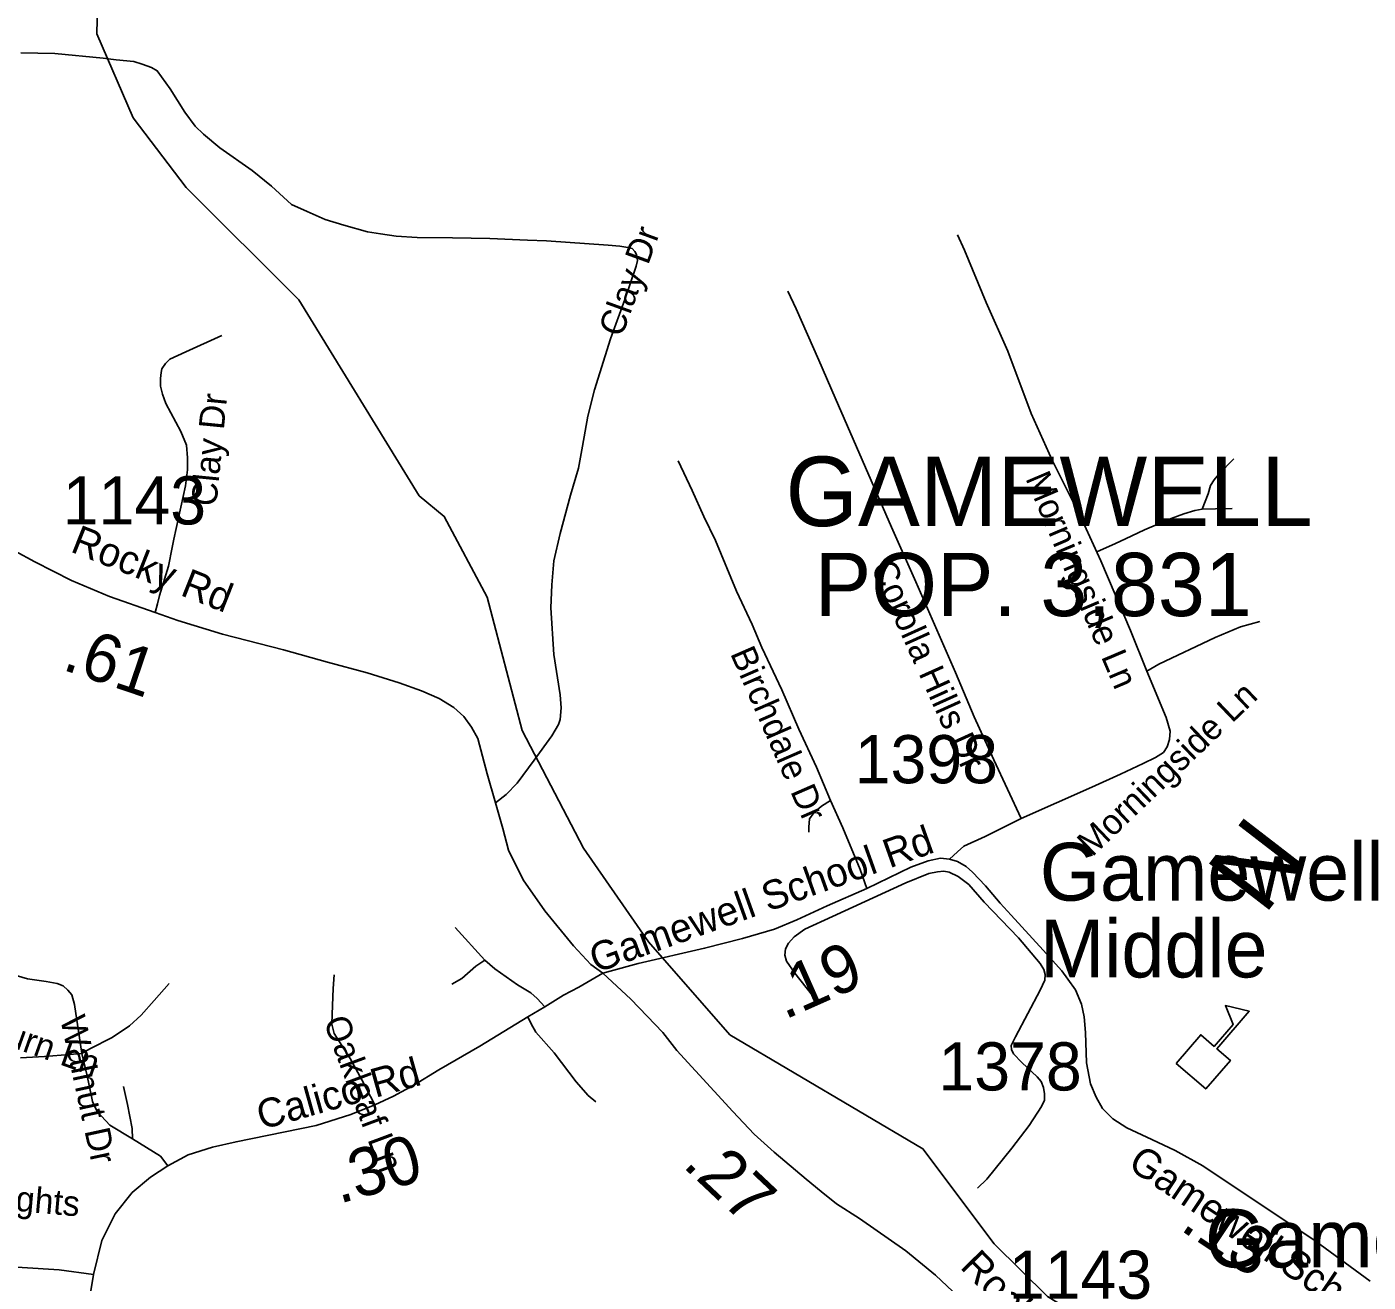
# Model space of a CAD drawing. Extents: x 1159738 to 1321356, y 736314 to 882035.
# Drawn here: x 1227136 to 1230616, y 781529 to 784785 of the extents above; entities that cross this region are included whole.
import ezdxf

# ---------------------------------------------------------------- set-up
doc = ezdxf.new("R2010")
doc.units = 0
for name, color, linetype in [('Exist Boundary Political Fire Districts Label', 7, 'Continuous'), ('Exist Civil Demographics City Label', 7, 'Continuous'), ('Exist Cultural Educational Facility Elementary Label', 7, 'Continuous'), ('Exist Cultural Educational Facility Middle CELL', 7, 'Continuous'), ('Exist Cultural Educational Facility Middle Label', 7, 'Continuous'), ('Exist Hydrographic Creek Single Shore', 7, 'Continuous'), ('Exist Hydrographic Misc Water Feature', 7, 'Continuous'), ('Exist Road Non-System Type 51', 7, 'Continuous'), ('Exist Road Non-System Type 51 Label', 7, 'Continuous'), ('Exist Road Secondary Mileage Hundredths English Label', 7, 'Continuous'), ('Exist Road Secondary Type 51 Attributed', 7, 'Continuous'), ('Exist Road Secondary Type 51 Label', 7, 'Continuous'), ('Exist Road Secondary Type 51 Number Label', 7, 'Continuous')]:
    doc.layers.add(name, color=color, linetype=linetype)

msp = doc.modelspace()

# ---------------------------------------------------------------- linework, layer by layer
at = {"layer": 'Exist Cultural Educational Facility Middle CELL'}
msp.add_lwpolyline([(1230117.6, 782096.4), (1230181.4, 782170.7), (1230216.3, 782140.6), (1230265.3, 782197.6), (1230245.5, 782246.6), (1230307.4, 782231.8), (1230223.6, 782134.4), (1230258.5, 782104.3), (1230194.6, 782030.1)], close=True, dxfattribs=at)
at = {"layer": 'Exist Hydrographic Creek Single Shore'}
msp.add_lwpolyline([(1231130.1, 780564), (1231004, 780616.7), (1230431, 781015.6), (1230170, 781257.2), (1229784, 781491.4), (1229646, 781628.8), (1229460.9, 781875.3), (1228960, 782171), (1228749, 782411.5), (1228579.9, 782654.6), (1228420.9, 782959.7), (1228330, 783306.2), (1228218.9, 783515.3), (1228153.9, 783569.1)], dxfattribs=at)
at = {"layer": 'Exist Hydrographic Misc Water Feature'}
msp.add_lwpolyline([(1228153.9, 783569.1), (1227841.9, 784077.5), (1227548.9, 784369), (1227411.8, 784549), (1227317.9, 784767.5), (1227323.9, 785026.8), (1227422.9, 785290.6), (1227668.9, 785774.9)], dxfattribs=at)
at = {"layer": 'Exist Road Non-System Type 51'}
for points in [[(1228351.5, 782772.3), (1228379.7, 782794.1), (1228407.8, 782823.1), (1228452.2, 782883), (1228498.4, 782946.6), (1228515.7, 782975.6), (1228519.3, 782988.3), (1228522, 783019.2), (1228519.3, 783052.7), (1228503, 783157.1), (1228495.7, 783278), (1228498.4, 783337.9), (1228503, 783400.5), (1228519.3, 783471.3), (1228546.5, 783570.2), (1228567.3, 783640.6), (1228577.3, 783697.7), (1228591.8, 783775.8), (1228609, 783843.8), (1228650.6, 783975.9), (1228687.8, 784078.5), (1228716.7, 784164.9), (1228720.3, 784179.4), (1228717.6, 784194.8), (1228713.1, 784203), (1228706.7, 784210.3), (1228695, 784213), (1228674.1, 784216.6), (1228644.2, 784219.3), (1228484.6, 784230.2), (1228435, 784231.9), (1228337.1, 784236.4), (1228240, 784238.2), (1228148.4, 784239.2), (1228094, 784242.8), (1228053.2, 784248.2), (1228019.7, 784253.7), (1227958, 784270.9), (1227910, 784285.4), (1227862.8, 784306.3), (1227822.4, 784324.4), (1227770.7, 784372.5), (1227720.8, 784412.4), (1227636.5, 784471.4), (1227594.7, 784506.8), (1227573, 784527.7), (1227545.8, 784564), (1227508, 784624.5), (1227474.4, 784671.6), (1227459, 784679.8), (1227435.4, 784688.9), (1227413.7, 784695.2), (1227367.4, 784699.8), (1227333.9, 784704.3), (1227208.2, 784716), (1227120.3, 784717.8)], [(1229550.8, 784246), (1229568.3, 784205.9), (1229624.8, 784070.7), (1229681.3, 783943.7), (1229741.8, 783782.3), (1229796.2, 783661.3), (1229875.1, 783504.3), (1229922.6, 783400.1), (1229999, 783219.6), (1230041.7, 783114)], [(1229110.2, 784099.4), (1229131.9, 784054.1), (1229190.6, 783920.4), (1229233.5, 783823), (1229312, 783642.4), (1229379.6, 783487.8), (1229442.4, 783345.9), (1229545.6, 783110.1), (1229594, 782995.1), (1229644.8, 782884.4), (1229715.4, 782731.7)], [(1227641.5, 783985), (1227548.1, 783942.3), (1227507.3, 783923.3), (1227495.5, 783912.4), (1227486.4, 783897.9), (1227484.6, 783888.8), (1227482.8, 783873.4), (1227482.8, 783853.4), (1227488.2, 783832.5), (1227496.4, 783808), (1227535.4, 783735.4), (1227549.9, 783700), (1227552.6, 783667.4), (1227552.6, 783636.5), (1227547.2, 783594.8), (1227517.3, 783456.3), (1227512.7, 783434.5), (1227503.7, 783386.4), (1227480.1, 783310.6), (1227474.6, 783288.8), (1227469.2, 783266.1)], [(1229095.1, 783065.5), (1229043.2, 783175.3), (1229017.8, 783235.2), (1228976.7, 783321.5), (1228922.4, 783453.2), (1228892.2, 783515.5), (1228862, 783582.9), (1228825.7, 783659.5)], [(1230185.2, 783534.5), (1230200.9, 783574.2), (1230206.9, 783596), (1230216.7, 783610.3), (1230228.7, 783625.4), (1230267.1, 783664.6)], [(1229911.7, 783423.5), (1229960.7, 783445.1), (1229986.4, 783456.9), (1230035.4, 783480.3), (1230104.6, 783509.7), (1230137.7, 783521.7), (1230166.3, 783530.8), (1230185.2, 783534.5), (1230219.8, 783535.3), (1230263.5, 783536.1)], [(1230041.7, 783114), (1230072.9, 783131.8), (1230219.1, 783201.7), (1230284.7, 783228.8), (1230335.3, 783243.2)], [(1229715.4, 782731.7), (1229899.1, 782812.7), (1229973.1, 782846.6), (1230032.1, 782874.3), (1230064.6, 782889.9), (1230085, 782903.2), (1230094.6, 782917.6), (1230100.7, 782936.9), (1230101.9, 782958.6), (1230092.2, 782993.5), (1230041.7, 783114)], [(1229220.8, 782778.4), (1229184.5, 782865), (1229139.2, 782963.9), (1229095.1, 783065.5)], [(1229220.8, 782778.4), (1229197.8, 782763.9), (1229177.9, 782746.4), (1229166.4, 782730.6), (1229164.6, 782708.9), (1229165.2, 782696.2)], [(1229220.8, 782778.4), (1229252.8, 782707.7), (1229297.6, 782599.4), (1229315.1, 782549.8)], [(1229715.4, 782731.7), (1229622.4, 782685.2), (1229567.3, 782660.4), (1229550.4, 782645.3), (1229529.9, 782626.5)], [(1229882.6, 782176.8), (1229879, 782217.4), (1229871.8, 782250), (1229856.7, 782287.5), (1229836.7, 782315.4), (1229821, 782336.5), (1229772.7, 782390.5), (1229689.9, 782481.3), (1229661.4, 782512.1), (1229622.9, 782557.3), (1229589.6, 782592.4), (1229573.3, 782606.9), (1229550.4, 782620.4)], [(1229191.1, 782252.2), (1229128.2, 782330.2), (1229106.5, 782361.7), (1229102.8, 782377.4), (1229104.6, 782393.8), (1229111.9, 782408.3), (1229127, 782424.6), (1229154.8, 782444.6), (1229226.2, 782477.8), (1229416.4, 782565.2), (1229476.3, 782588.8), (1229498.7, 782593.7), (1229515, 782594.9), (1229528.9, 782592.5), (1229552.5, 782581.6), (1229579.7, 782561), (1229619.6, 782515), (1229708.9, 782422.6), (1229765.1, 782356), (1229774.8, 782339.7), (1229777.8, 782327), (1229777.2, 782312.5), (1229765.1, 782286.5), (1229700.9, 782165.1), (1229690, 782142.7), (1229690.6, 782132.5), (1229695.5, 782121.6), (1229717.8, 782098.6), (1229757, 782062), (1229767.3, 782049.3), (1229774, 782034.2), (1229775.8, 782017.8), (1229776.4, 782001.5), (1229768.5, 781984.6), (1229736.5, 781935), (1229691.8, 781876.6), (1229626.5, 781796.1), (1229602.3, 781772.5)], [(1227278.9, 782122.6), (1227259.6, 782249.3), (1227252.4, 782274.1), (1227242.1, 782286.8), (1227230, 782297.7), (1227214.9, 782303.7), (1227186.5, 782308.6), (1227137.5, 782315.8), (1227108.5, 782324.3), (1227042, 782355.8), (1226957.4, 782402.9), (1226955, 782408.9), (1226955.6, 782423.5), (1226966.5, 782443.4), (1226999.7, 782491.6), (1227031.8, 782522.4), (1227068.6, 782549.7), (1227088.5, 782563.3)], [(1228324.5, 782364), (1228247.1, 782448.7)], [(1228238.7, 782301.7), (1228264.7, 782316.8), (1228301, 782348.3), (1228324.5, 782364)], [(1228324.5, 782364), (1228350.5, 782341.6), (1228408.6, 782300.5), (1228443.6, 782279.9), (1228460, 782264.8), (1228479.6, 782243.3)], [(1228038.7, 781989), (1228004.8, 782054.1), (1227974.6, 782109.2), (1227932.9, 782173.9), (1227926.9, 782198.1), (1227928.1, 782224.1), (1227930.5, 782290.9), (1227933, 782325.9)], [(1227504.8, 782303.6), (1227466.1, 782259.4), (1227432.3, 782222), (1227402.1, 782193.6), (1227357.4, 782163.3), (1227299.3, 782134.3), (1227278.9, 782122.6)], [(1228436.1, 782217.3), (1228444, 782198.7), (1228456.7, 782177.5), (1228504.4, 782123.6), (1228561.3, 782048.6), (1228592.7, 782012.9), (1228612.1, 781996.6)], [(1229885.4, 782097.8), (1229882.6, 782176.8)], [(1227278.9, 782122.6), (1227246.8, 782119.4), (1227181.5, 782114), (1227119.8, 782111.2)], [(1227501.9, 781830.7), (1227482.6, 781856.1), (1227410.1, 781900.7), (1227351.4, 781936.2), (1227318.2, 781971.9), (1227306.7, 781997.3), (1227292.2, 782064.5), (1227278.9, 782122.6)], [(1230055, 781898.8), (1229989.7, 781929.7), (1229953.6, 781952.9), (1229926.9, 781979.7), (1229910.6, 782008.8), (1229895.5, 782043.7), (1229885.4, 782097.8)], [(1227410.1, 781900.7), (1227409.5, 781927.9), (1227397.4, 781989.6), (1227386.5, 782036.8)]]:
    msp.add_lwpolyline(points, dxfattribs=at)
at = {"layer": 'Exist Road Secondary Type 51 Attributed'}
for points in [[(1227106, 783425.5), (1227156.3, 783397.3), (1227251.6, 783348.9), (1227350.6, 783307.9), (1227469.2, 783266.1), (1227527.7, 783245.1), (1227643.7, 783210.1), (1227801.5, 783169.1), (1227915.8, 783137.5), (1228018.7, 783109.4), (1228101.5, 783083.8), (1228159.5, 783063.3), (1228205.6, 783042.8), (1228243.6, 783020.1), (1228270, 782996.2), (1228289.6, 782968.9), (1228305.8, 782939), (1228330.6, 782847.6), (1228351.5, 782772.3), (1228370.6, 782705.5), (1228385.9, 782650), (1228423.5, 782572.3), (1228479.6, 782492.4), (1228553.9, 782401.9), (1228598.9, 782352.7), (1228629.9, 782330.3)], [(1228629.9, 782330.3), (1228649.3, 782335.7), (1228721.7, 782355.6), (1228894.4, 782395.4), (1228992.3, 782420.2), (1229075.8, 782445), (1229133.8, 782469.2), (1229212.1, 782505.5), (1229315.1, 782549.8), (1229429.4, 782605.7), (1229474.8, 782622.1), (1229506.8, 782628.7), (1229529.9, 782626.5), (1229550.4, 782620.4)], [(1228629.9, 782330.3), (1228567.7, 782294.6), (1228528.4, 782273.4), (1228479.6, 782243.3), (1228436.1, 782217.3), (1228310.9, 782141.1), (1228205.2, 782080.1), (1228140.1, 782040.3), (1228087.5, 782011.9), (1228038.7, 781989), (1227976.2, 781964), (1227886.3, 781935), (1227678.7, 781893.1), (1227617.2, 781879.6), (1227554.8, 781859.4), (1227501.9, 781830.7), (1227456.8, 781801.8), (1227408.8, 781761.4), (1227364.7, 781706.6), (1227330.1, 781637.4), (1227308.7, 781549)], [(1228629.9, 782330.3), (1228703.2, 782263.2), (1228745.6, 782218.8), (1228785.9, 782176.4), (1228822.2, 782130.1), (1228967.5, 781972), (1229022.9, 781913.1), (1229074.9, 781866.1), (1229157.8, 781796.2), (1229196.6, 781764), (1229236.7, 781732.4), (1229296.4, 781694), (1229416.7, 781610.3), (1229493.2, 781546.8), (1229596.8, 781449.6), (1229714.5, 781332)], [(1230621, 781531.9), (1230478.2, 781636.3), (1230187.4, 781830.7), (1230115.3, 781870.3), (1230055, 781898.8)], [(1227308.7, 781549), (1227219.7, 781561.4), (1227123.6, 781566.8), (1227018.1, 781572.7), (1226869.7, 781577.2), (1226710, 781582.8), (1226530.8, 781590.7), (1226349.5, 781603.1), (1226192, 781618.5), (1226038.8, 781631)], [(1227308.7, 781549), (1227302.3, 781506.2), (1227300.3, 781456.2), (1227303.2, 781336.1), (1227309, 781166.6), (1227311.9, 781044.5), (1227305.9, 780963.8), (1227303.3, 780924.7), (1227287.9, 780809.4), (1227272.6, 780715.6), (1227261.1, 780609.9), (1227251.4, 780496), (1227246.7, 780448.4), (1227235.1, 780411.9)]]:
    msp.add_lwpolyline(points, dxfattribs=at)

# ---------------------------------------------------------------- texts
at = {"layer": 'Exist Boundary Political Fire Districts Label'}
msp.add_text('N', height=196.8, rotation=52.3723, dxfattribs=at).set_placement((1230345.8, 782477.8))
at = {"layer": 'Exist Civil Demographics City Label'}
for s, height, p in [('GAMEWELL', 180.45, (1229104.4, 783490.2)), ('POP. 3,831', 164.04, (1229180.3, 783256.8))]:
    msp.add_text(s, height=height, dxfattribs=at).set_placement(p)
at = {"layer": 'Exist Cultural Educational Facility Elementary Label'}
msp.add_text('Gamewell', height=150, dxfattribs=at).set_placement((1230192.9, 781567.3))
at = {"layer": 'Exist Cultural Educational Facility Middle Label'}
for s, p in [('Gamewell', (1229764.1, 782518.7)), ('Middle', (1229764.1, 782319.5))]:
    msp.add_text(s, height=150, dxfattribs=at).set_placement(p)
at = {"layer": 'Exist Road Non-System Type 51 Label'}
for s, height, rotation, p in [('Clay Dr', 65.62, 69.9979, (1228679.2, 783977.7)), ('Clay Dr', 65.62, 84.4112, (1227627.5, 783539.8)), ('Morningside Ln', 65.617, 292.9944, (1229725.9, 783614.5)), ('Corolla Hills Dr', 65.617, 294.2841, (1229324.4, 783384.4)), ('Birchdale Dr', 65.617, 293.5709, (1228959.9, 783160.1)), ('Morningside Ln', 65.617, 43.7143, (1229899.7, 782630.4)), ('Left Turn Ln', 65.617, 340.4049, (1226864.6, 782220.6)), ('Walnut Dr', 65.62, 282.2321, (1227222.1, 782213.1)), ('Oakleaf Ln', 65.62, 290.4046, (1227905, 782206)), ('Gamewell Heights', 65.617, 355.0179, (1226561.2, 781761.2))]:
    msp.add_text(s, height=height, rotation=rotation, dxfattribs=at).set_placement(p)
at = {"layer": 'Exist Road Secondary Mileage Hundredths English Label'}
for s, rotation, p in [('.61', 341.2431, (1227224.5, 783119.1)), ('.19', 23.9243, (1229101.8, 782209)), ('.30', 15.7518, (1227946.2, 781732)), ('.27', 316.7012, (1228834.7, 781830.2)), ('.13', 326.2383, (1230124.9, 781666.4))]:
    msp.add_text(s, height=125, rotation=rotation, dxfattribs=at).set_placement(p)
at = {"layer": 'Exist Road Secondary Type 51 Label'}
for s, rotation, p in [('Rocky Rd', 338.3663, (1227246.2, 783425)), ('Gamewell School Rd', 19.6385, (1228612.6, 782330.4)), ('Calico Rd', 15.7047, (1227744.9, 781923.9)), ('Gamewell School Rd', 325.9745, (1229989.1, 781826.7)), ('Rocky Rd', 314.5328, (1229554.6, 781566.9))]:
    msp.add_text(s, height=75, rotation=rotation, dxfattribs=at).set_placement(p)
at = {"layer": 'Exist Road Secondary Type 51 Number Label'}
for s, p in [('1143', (1227229.1, 783494.5)), ('1398', (1229283.7, 782823.1)), ('1378', (1229501, 782026.2)), ('1143', (1229683.7, 781485.8))]:
    msp.add_text(s, height=125, dxfattribs=at).set_placement(p)

doc.saveas('drawing.dxf')
